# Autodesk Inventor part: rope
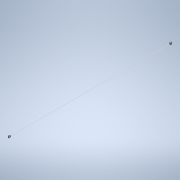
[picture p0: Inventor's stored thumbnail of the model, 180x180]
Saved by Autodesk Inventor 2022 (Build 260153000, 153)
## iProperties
Created: 2021-07
Part Number: rope
Material: Generic
Document SubType Name: Modeling
Designer: 91876
Density: 1 g/cm^3
Appearance: Default
Author: 91876
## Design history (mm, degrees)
sketch "Sketch1"
  geometry: C1 r 10 at (0, 0); 1 further point
  constraints: 1 centre point, 1 coincident
  dimensions: "d0" = 20 diameter of C1
extrude "Extrusion1" new body sketch "Sketch1" distance "d1" = 10000; taper "d2" = 0 deg
sketch "Sketch2"
  geometry: L1 (22.5, -50)-(-22.5, -50); L2 (-22.5, -50)-(-22.5, 50); L3 (-22.5, 50)-(22.5, 50); L4 (22.5, 50)-(22.5, -50); L5 (22.5, -50)-(-22.5, 50); L6 (-22.5, -50)-(22.5, 50); C1 r 10 at (0, 0) reference; 1 further point
  constraints: 12 end point, 2 midpoint, 2 parallel, 1 horizontal, 1 perpendicular
  dimensions: "d3" = 45 distance of L2.end L3.end; "d4" = 100 distance of L1.end L2.end
extrude "Extrusion2" join sketch "Sketch2" distance "d5" = 100; taper "d6" = 0 deg
sketch "Sketch3"
  geometry: L1 (22.5, -50)-(-22.5, -50); L2 (-22.5, -50)-(-22.5, 50); L3 (-22.5, 50)-(22.5, 50); L4 (22.5, 50)-(22.5, -50); L5 (22.5, -50)-(-22.5, 50); L6 (-22.5, -50)-(22.5, 50); 1 further point
  constraints: 12 end point, 2 midpoint, 2 parallel, 1 horizontal, 1 perpendicular
  dimensions: "d7" = 45 distance of L2.end L3.end; "d8" = 100 distance of L1.end L2.end
extrude "Extrusion3" join sketch "Sketch3" distance "d9" = 100; taper "d10" = 0 deg
sketch "Sketch4"
  geometry: L1 (0, 100)-(-100, 100) reference; L2 (-100, 0)-(-100, 100) reference; 2 further points
  dimensions: "d11" = 50 distance from line of L1 point (-50, 50); "d28" = 50 distance from line of point (-50, 50) L2
hole "Hole1" sketch "Sketch4" at (-50, 50) diameter "d12" = 63.075; stored, may be unused: countersink angle "d16" = 90 deg, drill point angle "d18" = 118 deg; dims "d13" = 6, "d14" = 4, "d15" = 2, "d17" = 8
sketch "Sketch5"
  geometry: L1 (0, -94.651)-(100, -94.651) reference; L2 (100, 5.349)-(100, -94.651) reference; 2 further points
  dimensions: "d26" = 50 distance from line of L1 point (50, -44.651); "d27" = 50 distance from line of L2 point (50, -44.651)
hole "Hole2" sketch "Sketch5" at (50, -44.651) diameter "d19" = 63.075; stored, may be unused: countersink angle "d23" = 90 deg, drill point angle "d25" = 118 deg; dims "d20" = 6, "d21" = 4, "d22" = 2, "d24" = 8
body "Solid1"
